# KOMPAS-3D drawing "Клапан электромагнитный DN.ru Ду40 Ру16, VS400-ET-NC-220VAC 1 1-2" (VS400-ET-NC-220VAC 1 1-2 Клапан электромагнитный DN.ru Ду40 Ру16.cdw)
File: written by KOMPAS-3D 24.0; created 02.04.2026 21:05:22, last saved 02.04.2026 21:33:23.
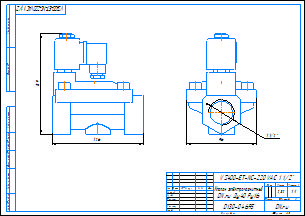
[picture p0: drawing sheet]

Document properties: c3d_UniqueCompID: ef56311e-7521-43dc-8291-0e6108b3d81d; Обозначение: VS400-ET-NC-220VAC 1; Наименование: Клапан электромагнитный DN.ru Ду25 Ру16; Автор: artio; Класс точности: c; Знак неуказанной шероховатости: Шероховатость не задана; Рассекать на разрезах: Да; c3d_UniqueCompID: ef56311e-7521-43dc-8291-0e6108b3d81d; Обозначение: VS400-ET-NC-220VAC 1-2; Наименование: Клапан электромагнитный DN.ru Ду15 Ру16; Автор: artio; Класс точности: c; Знак неуказанной шероховатости: Шероховатость не задана; Рассекать на разрезах: Да; c3d_UniqueCompID: ef56311e-7521-43dc-8291-0e6108b3d81d; Обозначение: VS400-ET-NC-220VAC 3-4; Наименование: Клапан электромагнитный DN.ru Ду20 Ру16; Автор: artio; Класс точности: c; Знак неуказанной шероховатости: Шероховатость не задана; Рассекать на разрезах: Да; c3d_UniqueCompID: ef56311e-7521-43dc-8291-0e6108b3d81d; Обозначение: VS400-ET-NC-220VAC 1 1-4; Наименование: Клапан электромагнитный DN.ru Ду32 Ру16; Автор: artio; Класс точности: c; Знак неуказанной шероховатости: Шероховатость не задана; Рассекать на разрезах: Да; c3d_UniqueCompID: ef56311e-7521-43dc-8291-0e6108b3d81d; Обозначение: VS400-ET-NC-220VAC 3-8; Наименование: Клапан электромагнитный DN.ru Ду10 Ру16; Автор: artio; Класс точности: c; Знак неуказанной шероховатости: Шероховатость не задана; Рассекать на разрезах: Да; c3d_UniqueCompID: ef56311e-7521-43dc-8291-0e6108b3d81d; Обозначение: VS400-ET-NC-220VAC 1 1-2; Наименование: Клапан электромагнитный DN.ru Ду40 Ру16; Автор: artio; Класс точности: c; Знак неуказанной шероховатости: Шероховатость не задана; Рассекать на разрезах: Да; Автор: artio; Форматы листов документа: A3; Полное имя файла: VS400-ET-NC-220VAC 1 1-2 Клапан электромагнитный DN.ru Ду40 Ру16.m3d; Масса: 2.321; Наименование: Клапан электромагнитный DN.ru Ду40 Ру16; Количество листов документа: 1; Примечание: D130-04695

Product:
- Body: Тело 1  | qty 1
    Масса: 4.144257
- Part/product: Клапан электромагнитный DN.ru Ду40 Ру16  | designation VS400-ET-NC-220VAC 1 1-2
    Масса: 2.321
    Раздел спецификации: Прочие изделия
    Примечание: D130-04695
    additional columns: ef56311e-7521-43dc-8291-0e6108b3d81d; VS400-ET-NC-220VAC 1 1-2; artio; c; Шероховатость не задана; Да

Views: Вид 1, Спереди
Referenced files in C:\Users\artio\OneDrive\Рабочий стол\Клапан электромагнитный DN.ru VS4x-xT-NC-x\DN10\: VS400-ET-NC-220VAC 3-8 Клапан электромагнитный DN.ru Ду10 Ру16.m3d, VS400-ET-NC-220VAC 3-8 Клапан электромагнитный DN.ru Ду10 Ру16.cdw
Referenced files in C:\Users\artio\OneDrive\Рабочий стол\Клапан электромагнитный DN.ru VS4x-xT-NC-x\DN40\: VS400-ET-NC-220VAC 1 1-2 Клапан электромагнитный DN.ru Ду40 Ру16.m3d
Referenced files in C:\Users\artio\OneDrive\Рабочий стол\Клапан электромагнитный DN.ru\VS400\VS400-ET-NC\VS400-ET-NC-220VAC\Ду40\: VS400-ET-NC-220VAC 1 1-2 Клапан электромагнитный DN.ru Ду40 Ру16.m3d
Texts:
  VS400-ET-NC-220VAC 1 1-2
  Клапан электромагнитный
  DN.ru Ду40 Ру16
  VS400-ET-NC-220VAC 1 1/2"
  VS400-ET-NC-220VAC 1 1/2"-
  Клапан электромагнитный DN.ru Ду40 Ру16
  VS400-ET-NC-220VAC 1 1-2 Клапан электромагнитный DN.ru Ду40 Ру16
Dimensions and other numbers on the sheet: 0; 3; 2; 4; 96; 1 1/2"; 1:1; 1; 2,32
